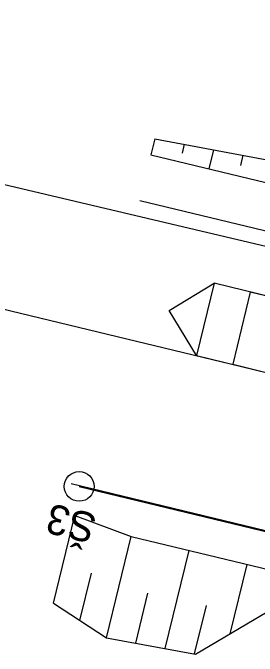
# Model space of a CAD drawing. Extents: x -748315 to -743169, y -1131781 to -1127091.
# Drawn here: x -747603.24 to -747599.14, y -1131709.4 to -1131698.59 of the extents above; entities that cross this region are included whole.
import ezdxf

# ---------------------------------------------------------------- set-up
doc = ezdxf.new("R2010")
doc.units = 0
for name, color, linetype in [('_Zabezpečovací zařízení', 7, 'Continuous'), ('_Zabezpečovací zařízení_trasa', 7, 'Continuous'), ('OSA_KOLEJ', 7, 'Continuous'), ('SMEROVE_A_VYSKOVE_VYROVNANI', 7, 'Continuous'), ('SVAH', 7, 'Continuous'), ('TRATIVOD', 7, 'Continuous'), ('TRATIVOD_POP', 7, 'Continuous')]:
    doc.layers.add(name, color=color, linetype=linetype)

msp = doc.modelspace()

# ---------------------------------------------------------------- linework, layer by layer
at = {"layer": '_Zabezpečovací zařízení'}
for p, q in [((-747600.617, -1131703.597), (-747599.863, -1131703.137)), ((-747599.863, -1131703.137), (-747600.157, -1131704.352)), ((-747598.648, -1131703.431), (-747599.863, -1131703.137)), ((-747599.255, -1131703.284), (-747599.549, -1131704.499)), ((-747600.157, -1131704.352), (-747600.617, -1131703.597)), ((-747600.157, -1131704.352), (-747598.942, -1131704.646))]:
    msp.add_line(p, q, dxfattribs=at)
msp.add_lwpolyline([(-747599.549, -1131704.499), (-747598.942, -1131704.646), (-747598.648, -1131703.431), (-747599.255, -1131703.284), (-747599.549, -1131704.499)], dxfattribs=at)
at = {"layer": '_Zabezpečovací zařízení_trasa'}
msp.add_lwpolyline([(-747299.39, -1131774.358), (-747312.964, -1131771.536), (-747335.194, -1131765.862), (-747431.496, -1131743.033), (-747485.589, -1131729.823), (-747529.872, -1131718.897), (-747616.745, -1131698.315), (-747822.016, -1131648.41), (-747861.482, -1131639.038), (-748013.304, -1131601.999), (-748116.903, -1131577.077), (-748210.219, -1131554.485), (-748277.301, -1131538.228)], dxfattribs=at)
at = {"layer": 'OSA_KOLEJ'}
msp.add_lwpolyline([(-747601.65, -1131703.991), (-747586.682, -1131707.613)], dxfattribs=at)
at = {"layer": 'SMEROVE_A_VYSKOVE_VYROVNANI'}
msp.add_lwpolyline([(-747648.511, -1131692.65), (-747601.65, -1131703.991)], dxfattribs=at)
at = {"layer": 'SVAH'}
for p, q in [((-747600.856, -1131700.71), (-747600.921, -1131700.978)), ((-747600.364, -1131700.802), (-747600.4, -1131700.949)), ((-747599.872, -1131700.894), (-747599.949, -1131701.213)), ((-747599.38, -1131700.986), (-747599.421, -1131701.158)), ((-747602.555, -1131708.516), (-747602.198, -1131707.04)), ((-747601.666, -1131709.095), (-747601.254, -1131707.391)), ((-747600.681, -1131709.276), (-747600.282, -1131707.626)), ((-747599.592, -1131709.026), (-747599.31, -1131707.862)), ((-747602.111, -1131708.805), (-747601.918, -1131708.01)), ((-747601.174, -1131709.185), (-747600.971, -1131708.347)), ((-747600.189, -1131709.367), (-747599.992, -1131708.555))]:
    msp.add_line(p, q, dxfattribs=at)
for points in [[(-747600.856, -1131700.71), (-747598.167, -1131701.213), (-747597.945, -1131701.692)], [(-747600.921, -1131700.978), (-747596.764, -1131701.983)], [(-747601.107, -1131701.745), (-747596.95, -1131702.751)], [(-747602.258, -1131706.504), (-747597.638, -1131707.622)], [(-747602.198, -1131707.04), (-747601.254, -1131707.391), (-747597.786, -1131708.23)], [(-747602.555, -1131708.516), (-747601.666, -1131709.095), (-747600.173, -1131709.37), (-747598.114, -1131708.151)]]:
    msp.add_lwpolyline(points, dxfattribs=at)
at = {"layer": 'TRATIVOD'}
msp.add_lwpolyline([(-747602.124, -1131706.551), (-747591.472, -1131709.129), (-747579.575, -1131712.008), (-747571.785, -1131715.287)], dxfattribs=at)
msp.add_circle((-747602.124, -1131706.551), 0.25, dxfattribs=at)

# ---------------------------------------------------------------- texts
at = {"layer": 'TRATIVOD_POP'}
msp.add_text('Š3', height=0.5, rotation=166, dxfattribs=at).set_placement((-747601.802, -1131707.031))

doc.saveas('drawing.dxf')
